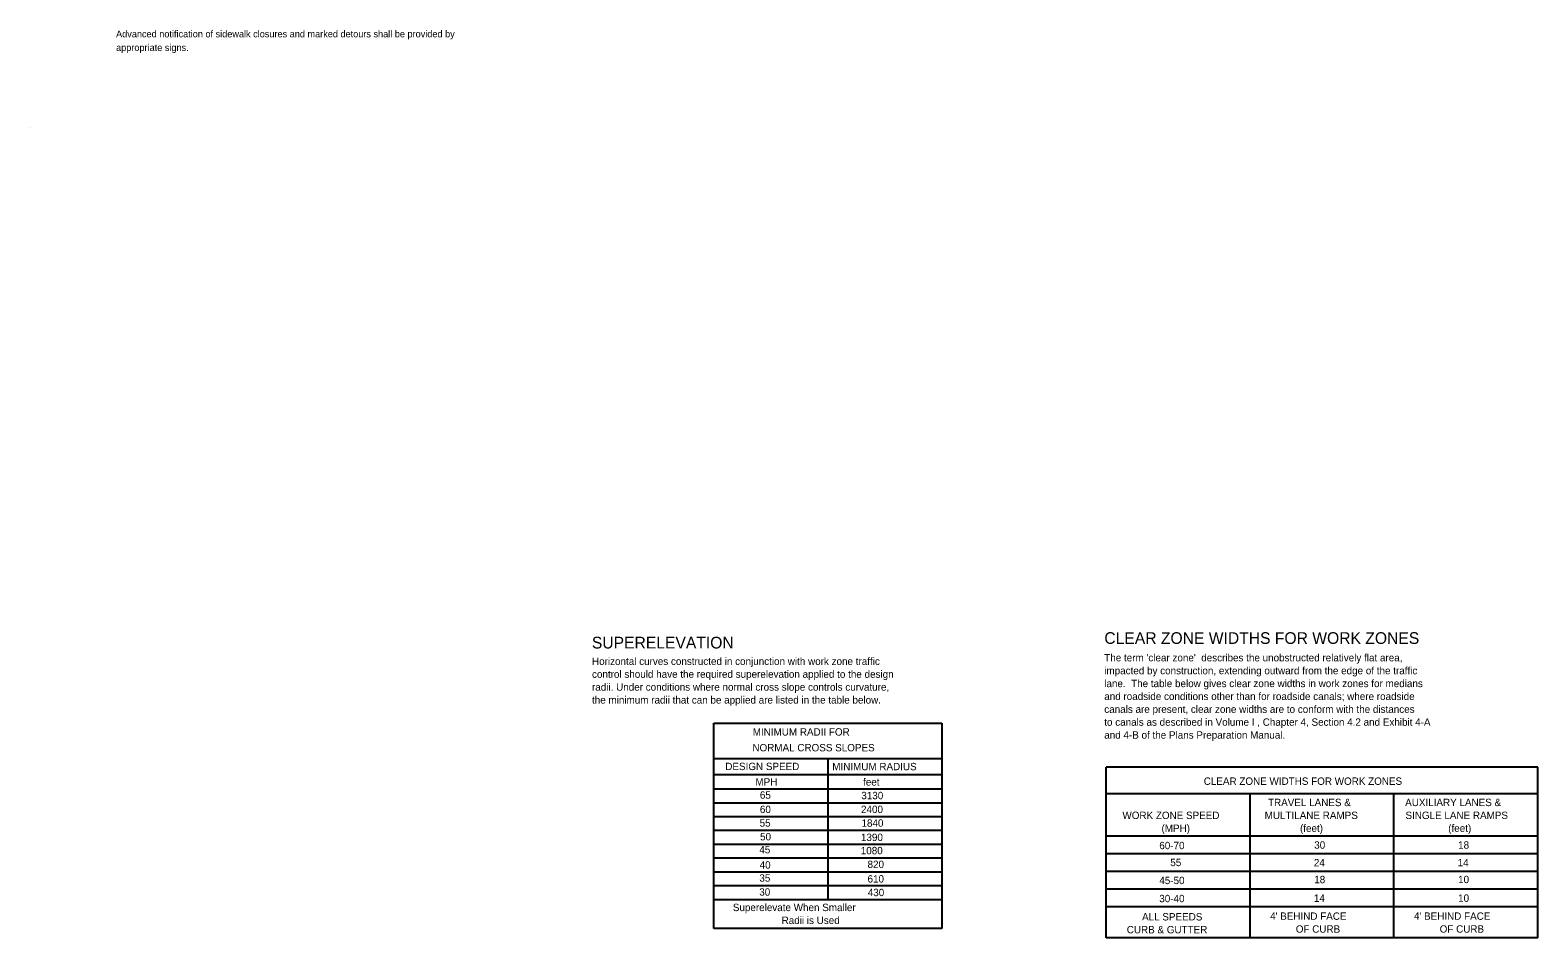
# Model space of a CAD drawing. Extents: x 10000 to 10773, y 9585 to 10515.
# Drawn here: x 10000 to 10773, y 9585 to 10050 of the extents above; entities that cross this region are included whole.
import ezdxf

# ---------------------------------------------------------------- set-up
doc = ezdxf.new("R2010")
doc.units = 0
for name, color, linetype in [('Dimension', 7, 'Continuous'), ('Patterning', 7, 'Continuous'), ('SupstrConc', 7, 'Continuous')]:
    doc.layers.add(name, color=color, linetype=linetype)

msp = doc.modelspace()

# ---------------------------------------------------------------- linework, layer by layer
at = {"layer": 'Dimension'}
for p, q in [((10350.41, 9694.65), (10467.12, 9694.65)), ((10350.41, 9589.32), (10350.41, 9694.65)), ((10467.12, 9694.65), (10467.12, 9589.32)), ((10350.21, 9676.52), (10466.93, 9676.52)), ((10408.77, 9676.52), (10408.77, 9604.26)), ((10350.41, 9668.25), (10467.12, 9668.25)), ((10772.57, 9671.98), (10551.4, 9671.98)), ((10551.4, 9584.52), (10551.4, 9671.98)), ((10772.57, 9584.56), (10772.57, 9671.98)), ((10350.41, 9660.88), (10467.12, 9660.88)), ((10772.57, 9658.39), (10551.4, 9658.39)), ((10625.12, 9584.52), (10625.12, 9658.39)), ((10698.85, 9584.54), (10698.85, 9658.39)), ((10350.41, 9653.8), (10467.12, 9653.8)), ((10350.41, 9646.73), (10467.12, 9646.73)), ((10350.41, 9639.65), (10467.12, 9639.65)), ((10772.57, 9636.62), (10551.4, 9636.62)), ((10350.41, 9632.57), (10467.12, 9632.57)), ((10772.57, 9627.57), (10551.4, 9627.57)), ((10350.41, 9625.49), (10467.12, 9625.49)), ((10772.57, 9618.51), (10551.4, 9618.51)), ((10350.41, 9618.42), (10467.12, 9618.42)), ((10350.41, 9611.34), (10467.12, 9611.34)), ((10350.41, 9604.26), (10467.12, 9604.26)), ((10772.57, 9609.45), (10551.4, 9609.45)), ((10772.57, 9600.39), (10551.4, 9600.39)), ((10467.12, 9589.32), (10350.41, 9589.32)), ((10772.57, 9584.54), (10551.4, 9584.54))]:
    msp.add_line(p, q, dxfattribs=at)
at = {"layer": 'Patterning'}
msp.add_line((10000, 10000), (10000, 10000), dxfattribs=at)
msp.add_line((10000, 10000), (10000, 10000), dxfattribs=at)

# ---------------------------------------------------------------- texts
at = {"layer": 'SupstrConc'}
for s, height, p in [('Advanced notification of sidewalk closures and marked detours shall be provided by ', 3.5, (10044.03, 10046.12)), ('appropriate signs.', 3.5, (10044.03, 10039.12)), ('SUPERELEVATION', 6, (10287.84, 9732.85)), ('CLEAR ZONE WIDTHS FOR WORK ZONES', 6, (10550.44, 9735.19)), ('Horizontal curves constructed in conjunction with work zone traffic', 3.78, (10287.91, 9724.41)), ("The term 'clear zone'  describes the unobstructed relatively flat area,", 3.78, (10550.39, 9726.23)), ('control should have the required superelevation applied to the design', 3.78, (10287.91, 9717.81)), ('impacted by construction, extending outward from the edge of the traffic', 3.78, (10550.39, 9719.63)), ('radii. Under conditions where normal cross slope controls curvature,', 3.78, (10287.91, 9711.21)), ('lane.  The table below gives clear zone widths in work zones for medians ', 3.78, (10550.39, 9713.03)), ('the minimum radii that can be applied are listed in the table below.', 3.78, (10287.91, 9704.61)), ('and roadside conditions other than for roadside canals; where roadside ', 3.78, (10550.39, 9706.43)), ('canals are present, clear zone widths are to conform with the distances', 3.78, (10550.39, 9699.83)), ('to canals as described in Volume I , Chapter 4, Section 4.2 and Exhibit 4-A', 3.78, (10550.39, 9693.23)), ('  MINIMUM RADII FOR', 3.78, (10367.45, 9688.19)), ('and 4-B of the Plans Preparation Manual.', 3.78, (10550.39, 9686.63)), ('NORMAL CROSS SLOPES', 3.78, (10370.1, 9680.12)), ('DESIGN SPEED', 3.78, (10356.21, 9670.51)), ('MINIMUM RADIUS  ', 3.78, (10411.01, 9670.43)), ('MPH', 3.78, (10371.62, 9662.59)), ('feet', 3.78, (10426.81, 9662.56)), ('CLEAR ZONE WIDTHS FOR WORK ZONES', 3.78, (10601.36, 9662.95)), ('65', 3.78, (10373.92, 9655.84)), ('3130', 3.78, (10425.91, 9655.58)), ('60', 3.78, (10373.93, 9648.48)), ('2400', 3.78, (10425.76, 9648.5)), ('TRAVEL LANES & ', 3.78, (10634.31, 9652.03)), ('AUXILIARY LANES & ', 3.78, (10704.59, 9652.05)), ('55', 3.78, (10373.8, 9641.52)), ('1840', 3.78, (10425.99, 9641.47)), ('WORK ZONE SPEED', 3.78, (10559.71, 9645.43)), ('(MPH)', 3.78, (10579.73, 9638.83)), ('MULTILANE RAMPS', 3.78, (10632.57, 9645.43)), ('(feet)', 3.78, (10650.69, 9638.83)), ('SINGLE LANE RAMPS', 3.78, (10704.73, 9645.45)), ('(feet)', 3.78, (10726.64, 9638.85)), ('50', 3.78, (10374.02, 9634.49)), ('1390', 3.78, (10425.71, 9634.16)), ('30', 3.78, (10657.99, 9630.22)), ('18', 3.78, (10731.71, 9630.24)), ('45', 3.78, (10373.64, 9627.82)), ('1080', 3.78, (10425.63, 9627.37)), ('60-70', 3.78, (10578.6, 9629.96)), ('40', 3.78, (10373.8, 9620)), ('820', 3.78, (10429.1, 9620.31)), ('55', 3.78, (10584.23, 9621.28)), ('24', 3.78, (10657.8, 9621.18)), ('14', 3.78, (10731.52, 9621.2)), ('35', 3.78, (10373.66, 9613.31)), ('610', 3.78, (10429.09, 9612.87)), ('45-50', 3.78, (10578.6, 9612.07)), ('18', 3.78, (10657.98, 9612.53)), ('10', 3.78, (10731.71, 9612.55)), ('30', 3.78, (10373.61, 9606.15)), ('430', 3.78, (10429.21, 9605.9)), ('30-40', 3.78, (10578.6, 9602.78)), ('14', 3.78, (10657.8, 9602.98)), ('10', 3.78, (10731.71, 9603)), ('Superelevate When Smaller ', 3.78, (10360.07, 9598.22)), ('Radii is Used', 3.78, (10385.06, 9591.62)), ('ALL SPEEDS', 3.78, (10569.76, 9593.43)), ("4' BEHIND FACE", 3.78, (10635.36, 9593.76)), ("4' BEHIND FACE", 3.78, (10709.08, 9593.78)), ('CURB & GUTTER ', 3.78, (10561.93, 9586.83)), ('OF CURB', 3.78, (10648.54, 9587.16)), ('OF CURB', 3.78, (10722.26, 9587.18))]:
    msp.add_text(s, height=height, dxfattribs=at).set_placement(p)

doc.saveas('drawing.dxf')
